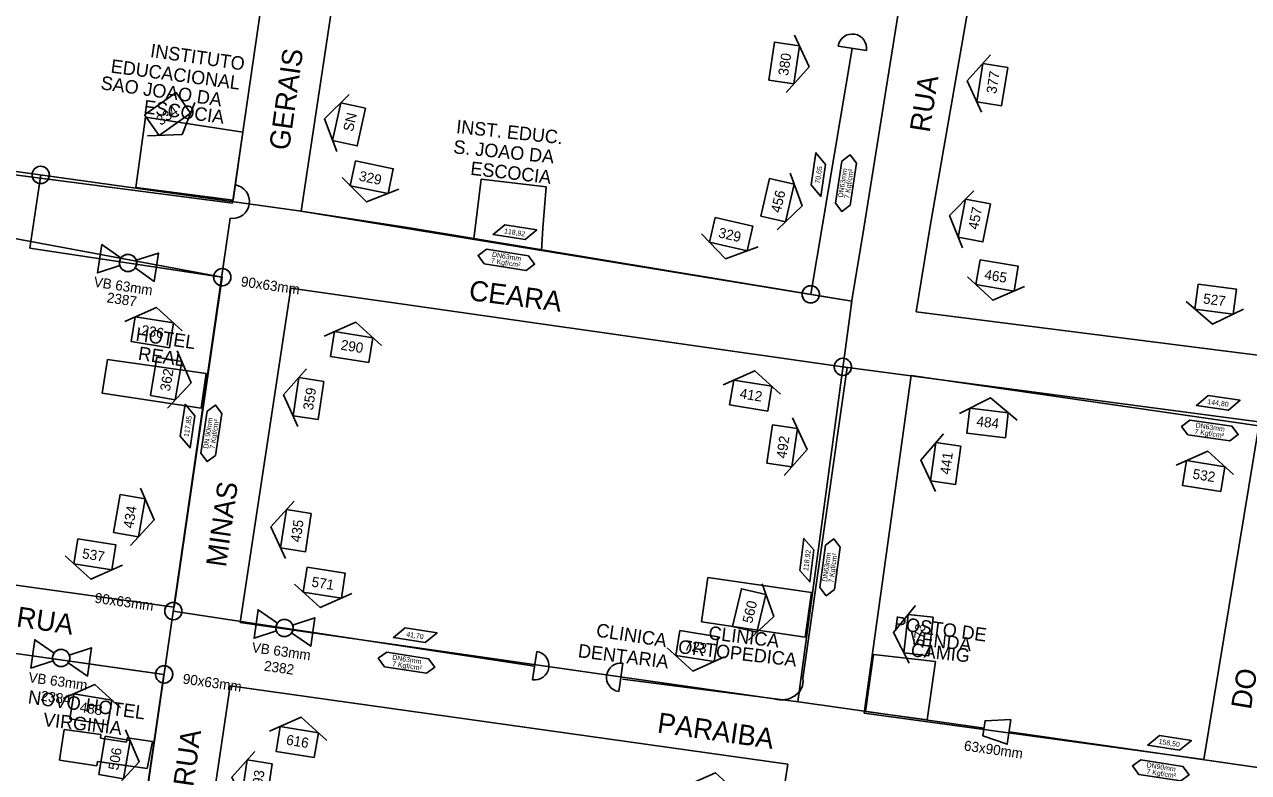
# Model space of a CAD drawing. Extents: x 325709 to 364434, y 7573432 to 7597073.
# Drawn here: x 338048.5 to 338412.3, y 7590340.1 to 7590562.4 of the extents above; entities that cross this region are included whole.
import ezdxf

# ---------------------------------------------------------------- set-up
doc = ezdxf.new("R2010")
doc.units = 0
for name, color, linetype in [('EDIFEXISTENT', 7, 'Continuous'), ('EDIFIDENTIF', 7, 'Continuous'), ('FORMATO', 7, 'Continuous'), ('LOGRADOURO', 7, 'Continuous'), ('LOGRADOURO_TEXTO', 7, 'Continuous'), ('NUM_REF', 7, 'Continuous'), ('SIMBOLO', 7, 'Continuous'), ('TEXTO', 7, 'Continuous'), ('TUBO_PEAD_GN_63', 7, 'Continuous'), ('TUBO_PEAD_GN_90', 7, 'Continuous'), ('VALVULA_PEAD_63', 7, 'Continuous'), ('VES - BLOQUEIIO', 7, 'Continuous')]:
    doc.layers.add(name, color=color, linetype=linetype)

# ---------------------------------------------------------------- blocks, each defined once
blk = doc.blocks.new('INTERLIGACAO')
at = {"layer": 'SIMBOLO'}
blk.add_circle((0, 0), 1.28, dxfattribs=at)
for start, end in [(0, 180), (180, 0)]:
    blk.add_arc((0, 0), 1.28, start, end, dxfattribs=at)
blk = doc.blocks.new('VALVULA_PEAD_DN_63')
at = {"layer": 'VALVULA_PEAD_63'}
for points in [[(-1.14, 0.57), (-4.25, 2.13), (-4.25, -2.13), (-1.14, -0.57)], [(-1.14, -0.57), (-4.25, -2.13), (-4.25, 2.13), (-1.14, 0.57)], [(1.14, -0.57), (4.25, -2.13), (4.25, 2.13), (1.14, 0.57)], [(1.14, -0.57), (4.25, -2.13), (4.25, 2.13), (1.14, 0.57)]]:
    blk.add_lwpolyline(points, dxfattribs=at)
blk.add_circle((0, 0), 1.28, dxfattribs=at)
for start, end in [(90, 270), (153.4349, 206.5651), (270, 90), (0, 26.5651), (333.4349, 0)]:
    blk.add_arc((0, 0), 1.28, start, end, dxfattribs=at)
blk = doc.blocks.new('NUM_REF')
at = {"layer": 'NUM_REF'}
blk.add_lwpolyline([(-4.3125, 0.9375), (0, 3.75), (4.3125, 0.9375)], dxfattribs=at)
blk.add_lwpolyline([(2.875, -1.875), (2.875, 1.875), (-2.875, 1.875), (-2.875, -1.875)], close=True, dxfattribs=at)

msp = doc.modelspace()

# ---------------------------------------------------------------- linework, layer by layer
at = {"layer": 'EDIFEXISTENT'}
for p, q in [((338081.52, 7590513.98), (338084.46, 7590534.89)), ((338084.46, 7590534.89), (338113.42, 7590530.42)), ((338113.42, 7590530.42), (338110.48, 7590510.22)), ((338110.48, 7590510.22), (338081.52, 7590513.98)), ((338182.43, 7590501.91), (338184.26, 7590516.42)), ((338184.26, 7590516.42), (338203.58, 7590514.14)), ((338203.58, 7590514.14), (338202.52, 7590501.91)), ((338182.43, 7590501.91), (338182.06, 7590498.8)), ((338202.52, 7590501.91), (338202.17, 7590495.26)), ((338071.56, 7590452.87), (338073.14, 7590462.85)), ((338073.14, 7590462.85), (338102.49, 7590458.7)), ((338102.49, 7590458.7), (338100.96, 7590448.36)), ((338100.96, 7590448.36), (338071.56, 7590452.87)), ((338251.55, 7590398.05), (338249.66, 7590384.84)), ((338282.38, 7590393.63), (338251.55, 7590398.05)), ((338282.38, 7590393.63), (338280.49, 7590380.32)), ((338280.49, 7590380.32), (338249.66, 7590384.84)), ((338249.66, 7590384.84), (338249.66, 7590384.84)), ((338298.5, 7590358.22), (338300.86, 7590375.16)), ((338300.86, 7590375.16), (338319.27, 7590373.14)), ((338319.27, 7590373.14), (338316.77, 7590355.73)), ((338316.77, 7590355.73), (338298.5, 7590358.22)), ((338058.88, 7590343.78), (338060.3, 7590352.86)), ((338060.3, 7590352.86), (338071.14, 7590351.41)), ((338071.14, 7590351.41), (338071.08, 7590350.31)), ((338071.08, 7590350.31), (338078.77, 7590349.13)), ((338078.77, 7590349.13), (338079, 7590350.43)), ((338079, 7590350.43), (338086.53, 7590349.29)), ((338086.53, 7590349.29), (338084.94, 7590341.32)), ((338069.99, 7590342.1), (338058.88, 7590343.78)), ((338070.19, 7590343.4), (338069.99, 7590342.1)), ((338084.94, 7590341.32), (338070.19, 7590343.4))]:
    msp.add_line(p, q, dxfattribs=at)
at = {"layer": 'LOGRADOURO'}
for p, q in [((338124.78, 7590608.94), (338110.28, 7590509.26)), ((338130.67, 7590506.93), (338145.55, 7590604.92)), ((338310.77, 7590582), (338297.99, 7590501.91)), ((338317.53, 7590501.91), (338330.93, 7590578.34)), ((338110.28, 7590509.26), (338009.03, 7590522.43)), ((338163.49, 7590501.91), (338130.67, 7590506.93)), ((338028.54, 7590501.91), (338107.26, 7590487.31)), ((338294.35, 7590480.19), (338163.49, 7590501.91)), ((338297.99, 7590501.91), (338294.22, 7590479.22)), ((338313.47, 7590477.02), (338317.53, 7590501.91)), ((338107.26, 7590487.31), (338092.92, 7590389.21)), ((338112.63, 7590384.71), (338127.63, 7590484.07)), ((338127.63, 7590484.07), (338292.96, 7590460.47)), ((338418.19, 7590463.77), (338313.47, 7590477.02)), ((338292.96, 7590460.47), (338279.85, 7590368.03)), ((338298.02, 7590357.71), (338312.03, 7590458.04)), ((338312.03, 7590458.04), (338415.38, 7590443.09)), ((338415.38, 7590443.09), (338399.04, 7590343.93)), ((338092.92, 7590389.21), (337991.83, 7590403.28)), ((337988.69, 7590383.52), (338089.86, 7590369.28)), ((338271.28, 7590362.02), (338112.63, 7590384.71)), ((338089.86, 7590369.28), (338075.44, 7590268.92)), ((338094.82, 7590266.47), (338109.59, 7590365.91)), ((338109.59, 7590365.91), (338275.35, 7590342.56)), ((338399.04, 7590343.93), (338298.02, 7590357.71)), ((338275.35, 7590342.56), (338259.48, 7590242.64))]:
    msp.add_line(p, q, dxfattribs=at)
for centre, radius, start, end in [((338274.83, 7590367.27), 5.08, 302.9981, 8.6397), ((338273.44, 7590368.88), 7.2, 252.5522, 305.2963)]:
    msp.add_arc(centre, radius, start, end, dxfattribs=at)
at = {"layer": 'SIMBOLO'}
for points in [[(338286.61, 7590520.79), (338285.18, 7590511.29), (338282.29, 7590514.76), (338283.72, 7590524.26)], [(338289.55, 7590509.33), (338291.43, 7590521.82), (338293.92, 7590523.65), (338293.92, 7590523.65), (338295.76, 7590521.17), (338293.88, 7590508.68), (338291.39, 7590506.84), (338291.39, 7590506.84)], [(338197.27, 7590498.47), (338187.78, 7590499.96), (338191.26, 7590502.83), (338200.76, 7590501.33)], [(338185.79, 7590495.6), (338198.26, 7590493.64), (338200.08, 7590491.14), (338200.08, 7590491.14), (338197.58, 7590489.32), (338185.11, 7590491.28), (338183.29, 7590493.78), (338183.29, 7590493.78)], [(338406.34, 7590447.82), (338396.83, 7590449.2), (338400.29, 7590452.11), (338409.8, 7590450.72)], [(338099.11, 7590446.06), (338097.68, 7590436.55), (338094.79, 7590440.02), (338096.22, 7590449.52)], [(338100.92, 7590434.97), (338102.8, 7590447.45), (338105.29, 7590449.29), (338105.29, 7590449.29), (338107.12, 7590446.8), (338105.24, 7590434.32), (338102.76, 7590432.48), (338102.76, 7590432.48)], [(338394.9, 7590444.82), (338407.39, 7590443), (338409.24, 7590440.52), (338409.24, 7590440.52), (338406.76, 7590438.67), (338394.27, 7590440.49), (338392.42, 7590442.97), (338392.42, 7590442.97)], [(338283.13, 7590406.28), (338281.87, 7590396.75), (338278.92, 7590400.17), (338280.17, 7590409.69)], [(338284.9, 7590395.11), (338286.55, 7590407.62), (338289, 7590409.5), (338289, 7590409.5), (338290.89, 7590407.05), (338289.23, 7590394.53), (338286.78, 7590392.65), (338286.78, 7590392.65)], [(338167.61, 7590378.73), (338158.12, 7590380.22), (338161.61, 7590383.09), (338171.1, 7590381.59)], [(338156.13, 7590375.87), (338168.6, 7590373.9), (338170.42, 7590371.4), (338170.42, 7590371.4), (338167.92, 7590369.58), (338155.45, 7590371.54), (338153.63, 7590374.05), (338153.63, 7590374.05)], [(338341.63, 7590355.9), (338334, 7590355.47), (338333.36, 7590351.02), (338340.58, 7590348.48)], [(338391.83, 7590346.75), (338382.33, 7590348.24), (338385.82, 7590351.11), (338395.31, 7590349.61)], [(338380.34, 7590343.88), (338392.82, 7590341.92), (338394.64, 7590339.42), (338394.64, 7590339.42), (338392.14, 7590337.6), (338379.66, 7590339.56), (338377.84, 7590342.06), (338377.84, 7590342.06)]]:
    msp.add_lwpolyline(points, close=True, dxfattribs=at)
at = {"layer": 'TUBO_PEAD_GN_63'}
for p, q in [((338282.18, 7590482.21), (338294.48, 7590555.24)), ((338290.31, 7590556), (338298.71, 7590554.62)), ((338130.67, 7590506.93), (337925.73, 7590535.43)), ((338130.66, 7590506.93), (338294.35, 7590480.19)), ((338107.1, 7590487.34), (338050.03, 7590495.93)), ((338278.38, 7590361.13), (338294.35, 7590480.19)), ((338291.73, 7590460.65), (338495.03, 7590433.8)), ((338092.71, 7590388.08), (338200.11, 7590371.73)), ((337988.85, 7590383.49), (338089.98, 7590369.26)), ((338200.76, 7590376.07), (338199.5, 7590367.66)), ((338225.12, 7590364.16), (338226.32, 7590372.58)), ((338278.52, 7590361.11), (338226.24, 7590367.85)), ((338278.52, 7590361.11), (338333.68, 7590353.25))]:
    msp.add_line(p, q, dxfattribs=at)
msp.add_lwpolyline([(338050.03, 7590495.93), (338050.03, 7590495.93), (338053.3, 7590517.69)], dxfattribs=at)
for centre, start, end in [((338294.51, 7590555.31), 350.6591, 170.6591), ((338200.13, 7590371.86), 261.4445, 81.4445), ((338225.72, 7590368.37), 81.854, 261.854)]:
    msp.add_arc(centre, 4.25, start, end, dxfattribs=at)
at = {"layer": 'TUBO_PEAD_GN_90'}
for p, q in [((338127.27, 7590626.47), (338111.07, 7590514.71)), ((338109.63, 7590504.81), (338081.27, 7590308.91)), ((338341.11, 7590352.19), (338453.43, 7590336.16))]:
    msp.add_line(p, q, dxfattribs=at)
msp.add_arc((338110.35, 7590509.76), 5, 261.7513, 81.7513, dxfattribs=at)

# ---------------------------------------------------------------- block references
at = {"layer": 'FORMATO'}
for p, xscale, yscale, rotation in [((338274.24, 7590550.95), 1.999999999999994, 1.9999999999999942, -98.39268905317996), ((338336.12, 7590544.52), 1.9999999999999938, 1.9999999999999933, 80.96768722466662), ((338090.99, 7590535.8), 1.9999999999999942, 1.9999999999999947, -144.77726212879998), ((338144.95, 7590532.72), 1.9999999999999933, 1.9999999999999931, 77.6324494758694), ((338151.69, 7590517), 1.9999999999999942, 1.999999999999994, 168.3826708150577), ((338272.31, 7590510.21), 1.999999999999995, 1.9999999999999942, -103.05837215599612), ((338330.79, 7590504.16), 1.9999999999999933, 1.9999999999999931, 78.90854849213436), ((338258.52, 7590500.07), 1.999999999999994, 1.999999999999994, 167.11519154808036), ((338337.57, 7590487.82), 1.9999999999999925, 1.9999999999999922, 170.4083240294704), ((338402.55, 7590480.78), 1.9999999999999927, 1.999999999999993, 172.33547002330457), ((338086.49, 7590470.92), 1.9999999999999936, 1.9999999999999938, -9.222222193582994), ((338145.74, 7590466.54), 1.9999999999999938, 1.999999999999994, -9.222222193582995), ((338090.58, 7590457.19), 1.9999999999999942, 1.9999999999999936, -99.71589097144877), ((338132.89, 7590451.22), 1.9999999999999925, 1.9999999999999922, 81.3795703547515), ((338264.35, 7590452.11), 1.9999999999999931, 1.9999999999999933, -9.222222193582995), ((338334.74, 7590443.96), 1.9999999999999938, 1.9999999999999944, -6.633415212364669), ((338273.69, 7590437.19), 1.9999999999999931, 1.9999999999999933, -98.15578933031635), ((338322.3, 7590431.93), 1.9999999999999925, 1.9999999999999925, 82.24847052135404), ((338398.98, 7590428.2), 1.9999999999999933, 1.9999999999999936, -9.222222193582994), ((338079.64, 7590416.43), 1.9999999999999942, 1.9999999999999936, -99.71589097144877), ((338129.16, 7590411.98), 1.9999999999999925, 1.9999999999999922, 81.3795703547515), ((338069.37, 7590404.95), 1.9999999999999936, 1.999999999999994, 170.91654670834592), ((338137.57, 7590396.52), 1.9999999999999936, 1.999999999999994, 170.91654670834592), ((338263.88, 7590388.23), 1.9999999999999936, 1.999999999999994, -103.3455902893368), ((338314.19, 7590380.93), 1.9999999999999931, 1.9999999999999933, 83.74012177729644), ((338248.35, 7590377.66), 1.9999999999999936, 1.999999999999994, 170.91654670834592), ((338068.19, 7590358.87), 1.9999999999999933, 1.9999999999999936, -9.222222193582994), ((338129.55, 7590349.16), 1.9999999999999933, 1.9999999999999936, -9.222222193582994), ((338075.2, 7590344.56), 1.9999999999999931, 1.999999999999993, -99.71589097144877), ((338117.53, 7590337.59), 1.9999999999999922, 1.999999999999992, 81.3795703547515), ((338252.71, 7590332.63), 1.9999999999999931, 1.9999999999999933, -9.222222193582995)]:
    msp.add_blockref('NUM_REF', p, dxfattribs=dict(at, xscale=xscale, yscale=yscale, rotation=rotation))
at = {"layer": 'SIMBOLO', "yscale": 2}
for p, xscale, rotation in [((338053.3, 7590517.69), 2, -8.011999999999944), ((338107.26, 7590487.31), 2, -8.011999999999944), ((338282.18, 7590482.21), 1.9999999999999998, 81.98800000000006), ((338291.73, 7590460.65), 1.9999999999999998, 81.98800000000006), ((338092.71, 7590388.08), 2, -8.011999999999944), ((338089.98, 7590369.26), 2, -8.011999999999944)]:
    msp.add_blockref('INTERLIGACAO', p, dxfattribs=dict(at, xscale=xscale, rotation=rotation))
at = {"layer": 'VALVULA_PEAD_63', "xscale": 1.999999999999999, "yscale": 1.9999999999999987, "rotation": -8.555472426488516}
msp.add_blockref('VALVULA_PEAD_DN_63', (338079.26, 7590491.53), dxfattribs=at)
at = {"layer": 'VES - BLOQUEIIO', "rotation": -8.011711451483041}
for p, xscale, yscale in [((338125.75, 7590383.05), 1.9999999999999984, 1.9999999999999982), ((338059.37, 7590374.15), 1.9999999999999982, 1.999999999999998)]:
    msp.add_blockref('VALVULA_PEAD_DN_63', p, dxfattribs=dict(at, xscale=xscale, yscale=yscale))

# ---------------------------------------------------------------- texts
for s, rotation, p in [('380', 81.6073, (338275.44, 7590547.03)), ('377', 80.9677, (338337.3, 7590541.67)), ('334', 35.2227, (338088.98, 7590532.23)), ('SN', 77.6324, (338146.09, 7590530.36)), ('329', 348.3827, (338147.72, 7590516.02)), ('456', 76.9416, (338273.18, 7590506.21)), ('457', 78.9085, (338331.87, 7590501.26)), ('329', 347.1152, (338254.53, 7590499.18)), ('465', 350.4083, (338333.63, 7590486.71)), ('VB 63mm', 351.4445, (338068.9, 7590484.49)), ('90x63mm', 351.988, (338112.64, 7590484.61)), ('2387', 351.4445, (338072.79, 7590479.86)), ('527', 352.3355, (338398.66, 7590479.53)), ('236', 350.7778, (338083.04, 7590470.18)), ('290', 350.7778, (338142.3, 7590465.8)), ('362', 80.2841, (338091.68, 7590453.25)), ('359', 81.3796, (338134.2, 7590447.61)), ('412', 350.7778, (338260.9, 7590451.36)), ('484', 353.3666, (338331.33, 7590443.06)), ('492', 81.8442, (338274.9, 7590433.29)), ('441', 82.2485, (338323.54, 7590428.52)), ('532', 350.7778, (338395.53, 7590427.45)), ('434', 80.2841, (338080.74, 7590412.49)), ('435', 81.3796, (338130.47, 7590408.37)), ('537', 350.9165, (338065.45, 7590403.8)), ('571', 350.9165, (338133.64, 7590395.37)), ('90x63mm', 351.988, (338069.2, 7590390.58)), ('560', 76.6544, (338264.74, 7590384.23)), ('573', 83.7401, (338315.61, 7590377.5)), ('VB 63mm', 351.9883, (338115.89, 7590375.88)), ('723', 350.9165, (338244.42, 7590376.51)), ('2382', 351.9883, (338119.53, 7590370.39)), ('VB 63mm', 351.9883, (338049.51, 7590366.98)), ('90x63mm', 351.988, (338095.36, 7590366.56)), ('2384', 351.9883, (338053.15, 7590361.49)), ('488', 350.7778, (338064.74, 7590358.13)), ('616', 350.7778, (338126.1, 7590348.42)), ('506', 80.2841, (338076.31, 7590340.62)), ('493', 81.3796, (338118.84, 7590333.98))]:
    msp.add_text(s, height=3, rotation=rotation).set_placement(p)
at = {"layer": 'EDIFIDENTIF'}
for s, rotation, p in [('INSTITUTO', 351.7272, (338085.68, 7590552.76)), ('EDUCACIONAL', 352.3878, (338073.95, 7590548.12)), ('SAO JOAO DA', 351.8721, (338070.94, 7590543.17)), ('ESCOCIA', 352.4083, (338083.72, 7590536.05)), ('INST. EDUC.', 353.9505, (338176.65, 7590530.15)), ('S. JOAO DA', 354.1817, (338175.83, 7590524.12)), ('ESCOCIA', 353.4821, (338180.87, 7590517.74)), ('HOTEL', 351.6698, (338081.35, 7590468.47)), ('REAL', 351.329, (338082.06, 7590462.8)), ('POSTO DE', 352.462, (338306.76, 7590382.61)), ('CLINICA', 351.2238, (338218.21, 7590380.54)), ('CLINICA', 352.9951, (338251.6, 7590379.74)), ('ORTOPEDICA', 353.4768, (338242.62, 7590375.59)), ('VENDA', 353.8344, (338311.4, 7590378.14)), ('CAMIG', 354.1206, (338311.81, 7590374.63)), ('DENTARIA', 352.7691, (338212.83, 7590374.39)), ('NOVO HOTEL', 352.1661, (338049.33, 7590360.63)), ('VIRGINIA', 353.4385, (338053.86, 7590353.94))]:
    msp.add_text(s, height=4, rotation=rotation, dxfattribs=at).set_placement(p)
at = {"layer": 'LOGRADOURO_TEXTO'}
for s, rotation, p in [('GERAIS', 81.9512, (338127.09, 7590524.77)), ('RUA', 80.9355, (338317.49, 7590530.1)), ('CEARA', 352.7882, (338180.36, 7590480.49)), ('MINAS', 81.8235, (338108.34, 7590400.93)), ('RUA', 351.463, (338045.82, 7590383.53)), ('DO', 80.6387, (338412.99, 7590358.62)), ('PARAIBA', 351.8604, (338236.33, 7590352.04)), ('RUA', 81.8615, (338098.61, 7590335.69))]:
    msp.add_text(s, height=6, rotation=rotation, dxfattribs=at).set_placement(p)
at = {"layer": 'TEXTO'}
for s, height, rotation, p in [('70,65', 1.5, 81.4445, (338284.85, 7590515.03)), ('DN63mm', 1.5, 81.4445, (338291.75, 7590510.91)), ('7 Kgf/cm²', 1.5, 81.4445, (338293.62, 7590510.57)), ('118,92', 1.5, 351.0538, (338190.94, 7590500.35)), ('7 Kgf/cm²', 1.5, 351.0538, (338187, 7590491.53)), ('DN63mm', 1.5, 351.0538, (338187.35, 7590493.4)), ('144,80', 1.5, 351.7268, (338400, 7590449.63)), ('117,85', 1.5, 81.4445, (338097.26, 7590439.72)), ('DN 90mm', 1.5, 81.4445, (338103.07, 7590436.26)), ('7 Kgf/cm²', 1.5, 81.4445, (338104.99, 7590436.21)), ('DN63mm', 1.5, 351.7268, (338396.49, 7590442.63)), ('7 Kgf/cm²', 1.5, 351.7268, (338396.15, 7590440.76)), ('118,92', 1.5, 82.4758, (338281.4, 7590399.91)), ('DN63mm', 1.5, 82.4758, (338287.06, 7590396.72)), ('7 Kgf/cm²', 1.5, 82.4758, (338288.94, 7590396.42)), ('41,70', 1.5, 351.0538, (338161.87, 7590380.52)), ('DN63mm', 1.5, 351.0538, (338157.7, 7590373.66)), ('7 Kgf/cm²', 1.5, 351.0538, (338157.68, 7590371.75)), ('63x90mm', 3, 351.9158, (338327.58, 7590346.69)), ('158,50', 1.5, 351.0538, (338385.5, 7590348.63)), ('DN90mm', 1.5, 351.0538, (338381.91, 7590341.68)), ('7 Kgf/cm²', 1.5, 351.0538, (338381.89, 7590339.76))]:
    msp.add_text(s, height=height, rotation=rotation, dxfattribs=at).set_placement(p)

doc.saveas('drawing.dxf')
